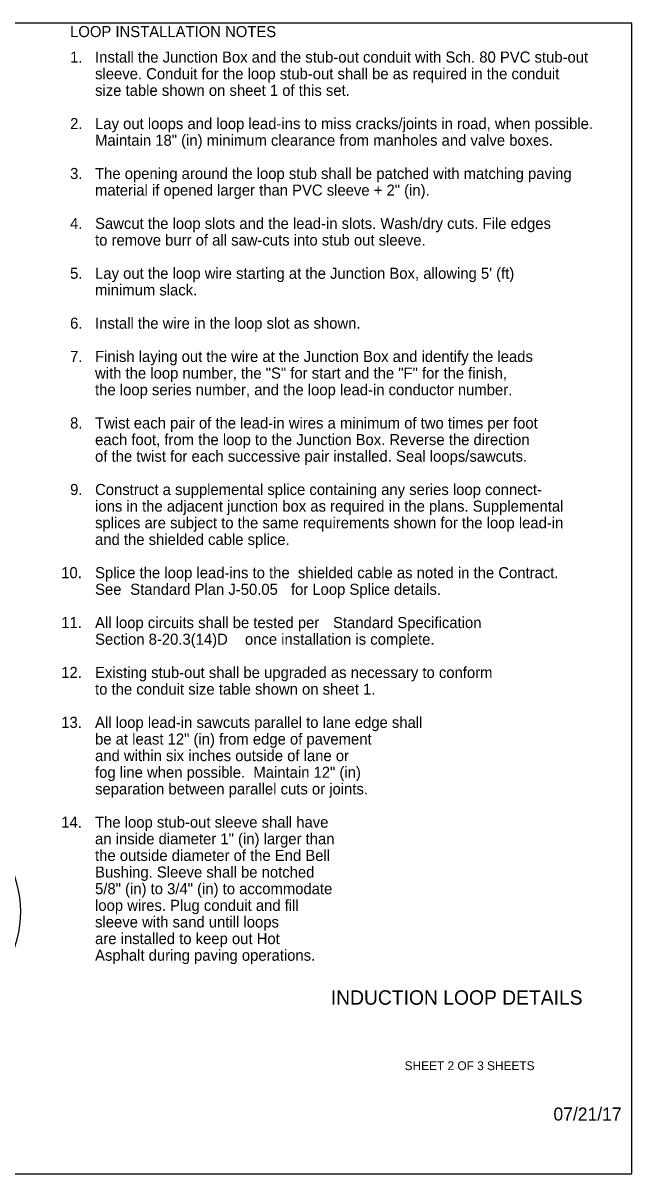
# Model space of a CAD drawing. Extents: x 99862 to 103151, y 100000 to 108153.
# Drawn here: x 102053 to 103151, y 103000 to 105076 of the extents above; entities that cross this region are included whole.
import ezdxf

# ---------------------------------------------------------------- set-up
doc = ezdxf.new("R2010")
doc.units = 0
for name, color, linetype in [('Level 1', 7, 'Continuous'), ('Level 15', 7, 'Continuous'), ('Level 20', 7, 'Continuous'), ('Level 60', 7, 'Continuous'), ('Level 62', 7, 'Continuous')]:
    doc.layers.add(name, color=color, linetype=linetype)

msp = doc.modelspace()

# ---------------------------------------------------------------- linework, layer by layer
at = {"layer": 'Level 1'}
msp.add_lwpolyline([(99862, 102999.5), (103151, 102999.5), (103151, 105075.5), (99862, 105075.5)], close=True, dxfattribs=at)
at = {"layer": 'Level 15'}
msp.add_ellipse((101610.8, 103471.8), major_axis=(-438.1, 0), ratio=0.659218, start_param=0.88715, end_param=3.725567, dxfattribs=at)
at = {"layer": 'Level 60'}
msp.add_line((103151, 105075.5), (103151, 105075.5), dxfattribs=at)

# ---------------------------------------------------------------- texts
at = {"layer": 'Level 15'}
msp.add_text('07/21/17', height=23.62, dxfattribs=at).set_placement((103009.4, 103095.8))
at = {"layer": 'Level 20'}
for s, p in [('LOOP INSTALLATION NOTES', (102137.9, 105050.1)), ('Install the Junction Box and the stub-out conduit with Sch. 80 PVC stub-out ', (102182.9, 105004.1)), ('1.', (102137.9, 105004.1)), ('sleeve. Conduit for the loop stub-out shall be as required in the conduit ', (102182.9, 104974.1)), ('size table shown on sheet 1 of this set.', (102182.9, 104944.1)), ('2.', (102137.9, 104884.1)), ('Lay out loops and loop lead-ins to miss cracks/joints in road, when possible. ', (102182.9, 104884.1)), ('Maintain 18" (in) minimum clearance from manholes and valve boxes.   ', (102182.9, 104854.1)), ('3.', (102137.9, 104794.1)), ('The opening around the loop stub shall be patched with matching paving ', (102182.9, 104794.1)), ('material if opened larger than PVC sleeve + 2" (in).', (102182.9, 104764.1)), ('4.', (102137.9, 104704.1)), ('Sawcut the loop slots and the lead-in slots. Wash/dry cuts. File edges ', (102182.9, 104704.1)), ('to remove burr of all saw-cuts into stub out sleeve.', (102182.9, 104674.1)), ('5.', (102137.9, 104614.1)), ("Lay out the loop wire starting at the Junction Box, allowing 5' (ft)", (102182.9, 104614.1)), ('minimum slack.', (102182.9, 104584.1)), ('6.', (102137.9, 104524.1)), ('Install the wire in the loop slot as shown.', (102182.9, 104524.1)), ('Finish laying out the wire at the Junction Box and identify the leads ', (102182.9, 104464.1)), ('7.', (102137.9, 104464.1)), ('with the loop number, the "S" for start and the "F" for the finish, ', (102182.9, 104434.1)), ('the loop series number, and the loop lead-in conductor number.   ', (102182.9, 104404.1)), ('8.', (102137.9, 104344.1)), ('Twist each pair of the lead-in wires a minimum of two times per foot  ', (102182.9, 104344.1)), ('each foot, from the loop to the Junction Box. Reverse the direction ', (102182.9, 104314.1)), ('of the twist for each successive pair installed. Seal loops/sawcuts.', (102182.9, 104284.1)), ('9.', (102137.9, 104224.1)), ('Construct a supplemental splice containing any series loop connect-', (102182.9, 104224.1)), ('ions in the adjacent junction box as required in the plans. Supplemental ', (102182.9, 104194.1)), ('splices are subject to the same requirements shown for the loop lead-in', (102182.9, 104164.1)), ('and the shielded cable splice.', (102182.9, 104134.1)), ('10.', (102121.9, 104074.1)), ('Splice the loop lead-ins to the  shielded cable as noted in the Contract.', (102182.9, 104074.1)), ('See ', (102182.9, 104044.1)), ('Standard Plan J-50.05', (102246.3, 104044.1)), (' for Loop Splice details.', (102528.6, 104044.1)), ('11.', (102121.9, 103984.1)), ('All loop circuits shall be tested per ', (102182.9, 103984.1)), ('Standard Specification', (102612, 103984.1)), ('Section 8-20.3(14)D ', (102182.9, 103954.1)), ('once installation is complete.', (102453.1, 103954.1)), ('12.', (102121.9, 103894.1)), ('Existing stub-out shall be upgraded as necessary to conform ', (102182.9, 103894.1)), ('to the conduit size table shown on sheet 1.', (102182.9, 103864.1)), ('13.', (102121.9, 103804.1)), ('All loop lead-in sawcuts parallel to lane edge shall ', (102182.9, 103804.1)), ('be at least 12" (in) from edge of pavement ', (102182.9, 103774.1)), ('and within six inches outside of lane or ', (102182.9, 103744.1)), ('fog line when possible.  Maintain 12" (in) ', (102182.9, 103714.1)), ('separation between parallel cuts or joints.  ', (102182.9, 103684.1)), ('14.', (102121.9, 103624.1)), ('The loop stub-out sleeve shall have ', (102182.9, 103624.1)), ('an inside diameter 1" (in) larger than ', (102182.9, 103594.1)), ('the outside diameter of the End Bell ', (102182.9, 103564.1)), ('Bushing. Sleeve shall be notched ', (102182.9, 103534.1)), ('5/8" (in) to 3/4" (in) to accommodate ', (102182.9, 103504.1)), ('loop wires. Plug conduit and fill ', (102182.9, 103474.1)), ('sleeve with sand untill loops ', (102182.9, 103444.1)), ('are installed to keep out Hot ', (102182.9, 103414.1)), ('Asphalt during paving operations.', (102182.9, 103384.1))]:
    msp.add_text(s, height=20, dxfattribs=at).set_placement(p)
at = {"layer": 'Level 62'}
for s, height, p in [('INDUCTION LOOP DETAILS', 26, (102607.9, 103304.8)), ('SHEET 2 OF 3 SHEETS', 16, (102741.1, 103186.8))]:
    msp.add_text(s, height=height, dxfattribs=at).set_placement(p)

doc.saveas('drawing.dxf')
